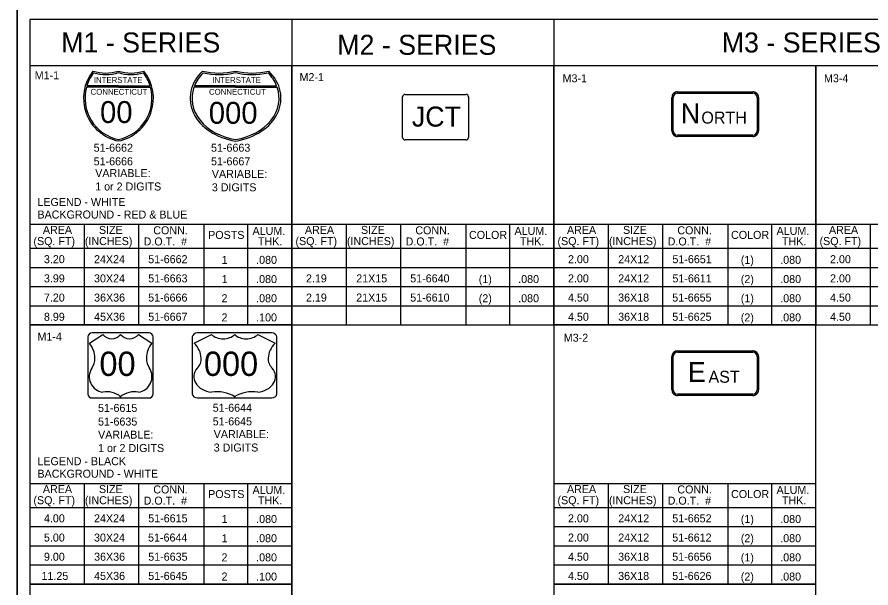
# Model space of a CAD drawing. Extents: x 0 to 2011, y -71 to 1183.
# Drawn here: x 0 to 341.3, y 164 to 392.2 of the extents above; entities that cross this region are included whole.
import ezdxf

# ---------------------------------------------------------------- set-up
doc = ezdxf.new("R2010")
doc.units = 0
for name, color, linetype in [('CT_Border_Perimeter_Shape', 7, 'Continuous'), ('CT_Construction', 7, 'Continuous'), ('Default', 7, 'Continuous'), ('Level 1', 7, 'Continuous'), ('Level 2', 7, 'Continuous'), ('Level 22', 7, 'Continuous'), ('Level 5', 7, 'Continuous')]:
    doc.layers.add(name, color=color, linetype=linetype)

msp = doc.modelspace()

# ---------------------------------------------------------------- linework, layer by layer
at = {"layer": 'CT_Border_Perimeter_Shape'}
msp.add_lwpolyline([(0, -0.97), (1270, -0.97), (1270, 829.03), (0, 829.03)], close=True, dxfattribs=at)
at = {"layer": 'CT_Construction'}
msp.add_lwpolyline([(0, 829.03), (1270, 829.03), (1270, 59.03), (0, 59.03)], close=True, dxfattribs=at)
at = {"layer": 'Default'}
for p, q in [((1262.03, 391.26), (5.05, 391.26)), ((28.92, 261.8), (34.26, 265.36)), ((48.53, 265.36), (53.87, 261.8)), ((70.77, 261.8), (77.71, 265.36)), ((96.26, 265.36), (103.2, 261.8)), ((41.36, 239.91), (41.39, 240.44)), ((41.4, 240.45), (41.37, 239.91)), ((54.37, 241.54), (54.37, 241.54)), ((86.94, 239.91), (86.99, 240.44)), ((87, 240.45), (86.96, 239.91)), ((103.86, 241.54), (103.86, 241.54))]:
    msp.add_line(p, q, dxfattribs=at)
for points in [[(28.35, 264.31), (28.35, 241.54)], [(52.74, 265.93), (29.97, 265.93)], [(54.37, 241.54), (54.37, 264.31)], [(70.03, 264.31), (70.03, 241.54)], [(101.74, 265.93), (72.14, 265.93)], [(103.86, 241.54), (103.86, 264.31)], [(29.97, 239.91), (41.36, 239.91)], [(41.37, 239.91), (52.74, 239.91)], [(72.14, 239.91), (86.94, 239.91)], [(86.96, 239.91), (101.74, 239.91)]]:
    msp.add_lwpolyline(points, dxfattribs=at)
for centre, radius, start, end in [((29.97, 264.31), 1.63, 90, 180), ((37.82, 267.99), 4.43, 216.4301, 323.5699), ((44.96, 267.99), 4.43, 216.4301, 323.5699), ((52.74, 264.31), 1.63, 0, 90), ((21.8, 255.89), 9.26, 359.7244, 39.6938), ((60.99, 255.89), 9.26, 140.3062, 180.2756), ((25.5, 255.33), 5.58, 320.9727, 5.2852), ((57.28, 255.33), 5.58, 174.7148, 219.0273), ((35.12, 248.44), 6.27, 147.4137, 262.1164), ((47.67, 248.44), 6.27, 277.8836, 32.5863), ((36, 234), 8.4, 50.0419, 101.9529), ((46.79, 234), 8.4, 78.0471, 129.856), ((29.97, 241.54), 1.63, 180, 270), ((52.74, 241.54), 1.63, 270, 360)]:
    msp.add_arc(centre, radius, start, end, dxfattribs=at)
for centre, major_axis, start_param, end_param in [((72.14, 264.31), (-2.11, 0), 4.712389, 6.283185), ((82.35, 267.99), (-5.76, 0), 0.635825, 2.505767), ((91.62, 267.99), (5.76, 0), 3.777418, 5.64736), ((101.74, 264.31), (2.11, 0), 0, 1.570796), ((61.51, 255.89), (12.03, 0), 6.278375, 6.975973), ((112.46, 255.89), (-12.03, 0), 5.590397, 6.287996), ((66.33, 255.33), (7.25, 0), 5.602031, 6.375429), ((107.65, 255.33), (-7.25, 0), 6.190941, 6.96434), ((78.83, 248.44), (-8.16, 0), 5.714447, 7.716386), ((95.14, 248.44), (8.16, 0), 4.849984, 6.851924), ((79.97, 234), (-10.92, 0), 4.014988, 4.921006), ((94, 234), (-10.92, 0), 4.503772, 5.408008), ((72.14, 241.54), (-2.11, 0), 0, 1.570796), ((101.74, 241.54), (2.11, 0), 4.712389, 6.283185)]:
    msp.add_ellipse(centre, major_axis=major_axis, ratio=0.769231, start_param=start_param, end_param=end_param, dxfattribs=at)
at = {"layer": 'Level 1'}
for p, q in [((264.01, 362.36), (294.13, 362.36)), ((154.13, 344.12), (154.13, 360.31)), ((155.14, 361.33), (179.44, 361.33)), ((180.45, 360.31), (180.45, 344.12)), ((261.77, 346.73), (261.77, 360.12)), ((262.34, 346.73), (262.34, 360.12)), ((264.01, 361.79), (294.13, 361.79)), ((295.8, 360.12), (295.8, 346.73)), ((296.37, 360.12), (296.37, 346.73)), ((294.13, 345.06), (264.01, 345.06)), ((179.44, 343.1), (155.14, 343.1)), ((294.13, 344.49), (264.01, 344.49)), ((261.77, 243.11), (261.77, 256.5)), ((262.34, 243.11), (262.34, 256.5)), ((264.01, 258.74), (294.13, 258.74)), ((264.01, 258.17), (294.13, 258.17)), ((295.8, 256.5), (295.8, 243.11)), ((296.37, 256.5), (296.37, 243.11)), ((29.97, 239.91), (29.97, 239.91)), ((72.86, 239.91), (72.86, 239.91)), ((294.13, 241.44), (264.01, 241.44)), ((294.13, 240.87), (264.01, 240.87))]:
    msp.add_line(p, q, dxfattribs=at)
for centre, radius, start, end in [((264.01, 360.12), 2.24, 90, 180.0015), ((294.13, 360.12), 2.24, 359.9993, 90), ((155.14, 360.31), 1.01, 90, 180), ((179.44, 360.31), 1.01, 0, 90), ((264.01, 360.12), 1.67, 90, 180), ((294.13, 360.12), 1.67, 0, 90), ((264.01, 346.73), 2.24, 179.998, 270), ((264.01, 346.73), 1.67, 180, 270), ((294.13, 346.73), 1.67, 270, 360), ((294.13, 346.73), 2.24, 270, 0.0005), ((155.14, 344.12), 1.01, 180, 270), ((179.44, 344.12), 1.01, 270, 360), ((264.01, 256.5), 2.24, 90, 180.0015), ((264.01, 256.5), 1.67, 90, 180), ((294.13, 256.5), 2.24, 359.9993, 90), ((294.13, 256.5), 1.67, 0, 90), ((264.01, 243.11), 2.24, 179.998, 270), ((264.01, 243.11), 1.67, 180, 270), ((294.13, 243.11), 1.67, 270, 360), ((294.13, 243.11), 2.24, 270, 0.0005)]:
    msp.add_arc(centre, radius, start, end, dxfattribs=at)
at = {"layer": 'Level 2'}
for p, q in [((40.52, 364.2), (27.73, 364.2)), ((40.52, 364.79), (27.9, 364.79)), ((40.52, 364.79), (53.15, 364.79)), ((40.52, 364.2), (53.32, 364.2)), ((87.34, 364.2), (70.71, 364.2)), ((87.34, 364.79), (70.93, 364.79)), ((87.34, 364.79), (103.76, 364.79)), ((87.34, 364.2), (103.98, 364.2)), ((5.05, 309.4), (109.8, 309.4)), ((26.8, 309.4), (26.8, 269.13)), ((48.55, 309.4), (48.55, 269.13)), ((74.65, 309.4), (74.65, 269.13)), ((92.05, 309.4), (92.05, 269.13)), ((109.8, 309.4), (214.55, 309.4)), ((131.55, 309.4), (131.55, 269.13)), ((153.3, 309.4), (153.3, 269.13)), ((179.4, 309.4), (179.4, 269.13)), ((196.8, 309.4), (196.8, 269.13)), ((214.55, 309.4), (319.3, 309.4)), ((236.3, 309.4), (236.3, 269.13)), ((258.05, 309.4), (258.05, 269.13)), ((284.15, 309.4), (284.15, 269.13)), ((301.55, 309.4), (301.55, 269.13)), ((319.3, 309.4), (424.05, 309.4)), ((341.05, 309.4), (341.05, 269.13)), ((5.05, 299.81), (109.8, 299.81)), ((109.8, 299.81), (214.55, 299.81)), ((214.55, 299.81), (319.3, 299.81)), ((319.3, 299.81), (424.05, 299.81)), ((5.05, 292.14), (109.8, 292.14)), ((109.8, 292.14), (214.55, 292.14)), ((214.55, 292.14), (319.3, 292.14)), ((319.3, 292.14), (424.05, 292.14)), ((5.05, 284.47), (109.8, 284.47)), ((109.8, 284.47), (214.55, 284.47)), ((214.55, 284.47), (319.3, 284.47)), ((319.3, 284.47), (424.05, 284.47)), ((5.05, 276.8), (109.8, 276.8)), ((109.8, 276.8), (214.55, 276.8)), ((214.55, 276.8), (319.3, 276.8)), ((319.3, 276.8), (424.05, 276.8)), ((5.05, 205.78), (109.8, 205.78)), ((26.8, 205.78), (26.8, 165.5)), ((48.55, 205.78), (48.55, 165.5)), ((74.65, 205.78), (74.65, 165.5)), ((92.05, 205.78), (92.05, 165.5)), ((214.55, 205.78), (319.3, 205.78)), ((236.3, 205.78), (236.3, 165.5)), ((258.05, 205.78), (258.05, 165.5)), ((284.15, 205.78), (284.15, 165.5)), ((301.55, 205.78), (301.55, 165.5)), ((5.05, 196.19), (109.8, 196.19)), ((214.55, 196.19), (319.3, 196.19)), ((5.05, 188.52), (109.8, 188.52)), ((214.55, 188.52), (319.3, 188.52)), ((5.05, 180.85), (109.8, 180.85)), ((214.55, 180.85), (319.3, 180.85)), ((5.05, 173.18), (109.8, 173.18)), ((214.55, 173.18), (319.3, 173.18))]:
    msp.add_line(p, q, dxfattribs=at)
for points in [[(109.8, 372.75), (5.05, 372.75), (5.05, 269.13), (109.8, 269.13)], [(214.55, 372.75), (109.8, 372.75), (109.8, 269.13), (214.55, 269.13)], [(319.3, 372.75), (214.55, 372.75), (214.55, 269.13), (319.3, 269.13)], [(424.05, 372.75), (319.3, 372.75), (319.3, 269.13), (424.05, 269.13)], [(109.8, 269.13), (5.05, 269.13), (5.05, 165.5), (109.8, 165.5)], [(319.3, 269.13), (214.55, 269.13), (214.55, 165.5), (319.3, 165.5)], [(109.8, 165.5), (5.05, 165.5), (5.05, 61.88), (109.8, 61.88)], [(319.3, 165.5), (214.55, 165.5), (214.55, 61.88), (319.3, 61.88)]]:
    msp.add_lwpolyline(points, close=True, dxfattribs=at)
for centre, radius, start, end in [((44.02, 359.78), 17.46, 141.669, 258.4631), ((44.02, 359.78), 16.88, 142.9959, 162.7368), ((35.42, 387.31), 17.46, 253.0091, 286.9909), ((35.42, 387.31), 18.04, 254.2923, 286.427), ((37.03, 359.78), 17.46, 281.5369, 38.331), ((45.63, 387.31), 17.46, 253.0091, 286.9909), ((45.63, 387.31), 18.04, 253.573, 285.7077), ((37.03, 359.78), 16.88, 17.2632, 37.0041), ((44.02, 359.78), 16.88, 164.7947, 258.0595), ((37.03, 359.78), 16.88, 281.9405, 15.2053)]:
    msp.add_arc(centre, radius, start, end, dxfattribs=at)
for centre, major_axis, start_param, end_param in [((91.88, 359.78), (22.7, 0), 2.472591, 4.511031), ((91.88, 359.78), (21.94, 0), 2.495749, 2.840293), ((80.71, 387.31), (22.7, 0), 4.415841, 5.008937), ((80.71, 387.31), (23.46, 0), 4.438239, 4.999095), ((82.8, 359.78), (-22.7, 0), 1.772154, 3.810595), ((93.98, 387.31), (22.7, 0), 4.415841, 5.008937), ((93.98, 387.31), (23.46, 0), 4.425683, 4.986539), ((82.8, 359.78), (-21.94, 0), 3.442893, 3.787436), ((91.88, 359.78), (21.94, 0), 2.876209, 4.503987), ((82.8, 359.78), (-21.94, 0), 1.779198, 3.406976)]:
    msp.add_ellipse(centre, major_axis=major_axis, ratio=0.769231, start_param=start_param, end_param=end_param, dxfattribs=at)
at = {"layer": 'Level 5'}
for p, q in [((5.05, 391.26), (5.05, 61.88)), ((109.8, 391.26), (109.8, 61.88)), ((214.55, 391.26), (214.55, 61.88))]:
    msp.add_line(p, q, dxfattribs=at)
msp.add_lwpolyline([(5.05, 391.26), (5.05, 372.75)], dxfattribs=at)

# ---------------------------------------------------------------- texts
at = {"layer": 'Level 1'}
for s, p in [('M1 - SERIES', (17.63, 378.07)), ('M3 - SERIES', (281.7, 378.07)), ('M2 - SERIES', (127.99, 377.13)), ('N', (265.34, 349.79)), ('E', (268.19, 246.32))]:
    msp.add_text(s, height=8, dxfattribs=at).set_placement(p)
at = {"layer": 'Level 2'}
for s, height, p in [('M1-1', 3.2, (7.05, 367.33)), ('M2-1', 3.2, (112.92, 366.62)), ('M3-1', 3.2, (218.08, 366.15)), ('M3-4', 3.2, (322.57, 366.15)), ('INTERSTATE', 2.333, (30.71, 365.89)), ('INTERSTATE', 2.333, (78.06, 365.89)), ('CONNECTICUT', 2.3328, (29.37, 361.17)), ('CONNECTICUT', 2.3328, (76.72, 361.17)), ('00', 8.748, (33.16, 349.87)), ('000', 8.748, (76.63, 349.56)), ('JCT', 8, (157.82, 348.43)), ('ORTH', 4.8, (273.55, 349.63)), ('51-6662', 3.2, (30.62, 338.39)), ('51-6663', 3.2, (77.53, 338.39)), ('51-6666', 3.2, (30.62, 332.94)), ('51-6667', 3.2, (77.53, 332.94)), ('VARIABLE: ', 3.2, (31.23, 328.24)), ('VARIABLE: ', 3.2, (77.86, 327.92)), ('1 or 2 DIGITS', 3.2, (31.23, 322.88)), ('3 DIGITS', 3.2, (77.86, 322.56)), ('LEGEND - WHITE', 3.2, (8.13, 316.67)), ('BACKGROUND - RED & BLUE', 3.2, (8.13, 311.67)), ('AREA', 3.2, (10.32, 305.52)), ('SIZE', 3.2, (32.73, 305.52)), ('CONN.', 3.2, (54.45, 305.37)), ('ALUM.', 3.2, (94.12, 305.14)), ('AREA', 3.2, (115.07, 305.52)), ('SIZE', 3.2, (137.48, 305.52)), ('CONN.', 3.2, (159.2, 305.37)), ('ALUM.', 3.2, (198.86, 305.14)), ('AREA', 3.2, (219.82, 305.52)), ('SIZE', 3.2, (242.23, 305.52)), ('CONN.', 3.2, (263.95, 305.37)), ('ALUM.', 3.2, (303.61, 305.14)), ('AREA', 3.2, (324.56, 305.52)), ('(SQ. FT)', 3.2, (6.54, 301.05)), ('(INCHES)', 3.2, (27.1, 301.05)), ('D.O.T.  #', 3.2, (50.59, 300.9)), ('POSTS', 3.2, (76.38, 303.52)), ('THK.', 3.2, (96.29, 301)), ('(SQ. FT)', 3.2, (111.29, 301.05)), ('(INCHES)', 3.2, (131.85, 301.05)), ('D.O.T.  #', 3.2, (155.33, 300.9)), ('COLOR', 3.2, (180.67, 303.52)), ('THK.', 3.2, (201.04, 301)), ('(SQ. FT)', 3.2, (216.03, 301.05)), ('(INCHES)', 3.2, (236.6, 301.05)), ('D.O.T.  #', 3.2, (260.08, 300.9)), ('COLOR', 3.2, (285.42, 303.52)), ('THK.', 3.2, (305.79, 301)), ('(SQ. FT)', 3.2, (320.78, 301.05)), ('M1-4', 3.2, (8.15, 262.85)), ('M3-2', 3.2, (218.55, 262.41)), ('AST', 4.8, (276.4, 246.01)), ('51-6615', 3.2, (32.36, 234.33)), ('51-6644', 3.2, (78.21, 234.41)), ('51-6635', 3.2, (32.36, 228.88)), ('51-6645', 3.2, (78.21, 228.96)), ('VARIABLE: ', 3.2, (32.38, 223.66)), ('VARIABLE: ', 3.2, (78.61, 223.86)), ('1 or 2 DIGITS', 3.2, (32.38, 218.3)), ('3 DIGITS', 3.2, (78.61, 218.5)), ('LEGEND - BLACK', 3.2, (8.13, 213.04)), ('BACKGROUND - WHITE', 3.2, (8.13, 208.04)), ('AREA', 3.2, (10.32, 201.9)), ('SIZE', 3.2, (32.73, 201.9)), ('CONN.', 3.2, (54.45, 201.74)), ('AREA', 3.2, (219.82, 201.9)), ('SIZE', 3.2, (242.23, 201.9)), ('CONN.', 3.2, (263.95, 201.74)), ('POSTS', 3.2, (76.38, 199.9)), ('ALUM.', 3.2, (94.12, 201.52)), ('COLOR', 3.2, (285.42, 199.9)), ('ALUM.', 3.2, (303.61, 201.52)), ('(SQ. FT)', 3.2, (6.54, 197.43)), ('(INCHES)', 3.2, (27.1, 197.43)), ('D.O.T.  #', 3.2, (50.59, 197.27)), ('THK.', 3.2, (96.29, 197.38)), ('(SQ. FT)', 3.2, (216.03, 197.43)), ('(INCHES)', 3.2, (236.6, 197.43)), ('D.O.T.  #', 3.2, (260.08, 197.27)), ('THK.', 3.2, (305.79, 197.38))]:
    msp.add_text(s, height=height, dxfattribs=at).set_placement(p)
at = {"layer": 'Level 22'}
for s, p in [('00', (32.92, 248.73)), ('000', (74.69, 248.73))]:
    msp.add_text(s, height=9.72, dxfattribs=at).set_placement(p)
at = {"layer": 'Level 5'}
for s, p in [(' 3.20', (9.55, 293.81)), ('24X24', (30.76, 293.81)), ('51-6662', (52.43, 293.81)), (' 2.00', (219.05, 293.81)), ('24X12', (240.32, 293.81)), ('51-6651', (261.98, 293.81)), (' 2.00', (323.8, 293.81)), ('1', (81.79, 293.55)), ('.080', (95.57, 293.55)), ('(1)', (289.31, 293.55)), ('.080', (305.07, 293.55)), (' 3.99', (9.55, 286.14)), ('30X24', (30.76, 286.14)), ('51-6663', (52.43, 286.14)), ('1', (81.79, 285.87)), ('.080', (95.57, 285.87)), (' 2.19', (114.3, 286.14)), ('21X15', (135.57, 286.14)), ('51-6640', (157.17, 286.14)), ('(1)', (184.56, 285.87)), ('.080', (200.32, 285.87)), (' 2.00', (219.05, 286.14)), ('24X12', (240.32, 286.14)), ('51-6611', (261.98, 286.14)), ('(2)', (289.31, 285.87)), ('.080', (305.07, 285.87)), (' 2.00', (323.8, 286.14)), (' 7.20', (9.55, 278.47)), ('36X36', (30.79, 278.47)), ('51-6666', (52.4, 278.47)), ('2', (81.73, 278.2)), ('.080', (95.57, 278.2)), (' 2.19', (114.3, 278.47)), ('21X15', (135.57, 278.47)), ('51-6610', (157.17, 278.47)), ('(2)', (184.56, 278.2)), ('.080', (200.32, 278.2)), (' 4.50', (219.05, 278.47)), ('36X18', (240.29, 278.47)), ('51-6655', (261.92, 278.47)), ('(1)', (289.31, 278.2)), ('.080', (305.07, 278.2)), (' 4.50', (323.8, 278.47)), (' 8.99', (9.55, 270.79)), ('45X36', (30.79, 270.79)), ('51-6667', (52.43, 270.79)), ('2', (81.73, 270.53)), ('.100', (95.57, 270.53)), (' 4.50', (219.05, 270.79)), ('36X18', (240.29, 270.79)), ('51-6625', (261.92, 270.79)), ('(2)', (289.31, 270.53)), ('.080', (305.07, 270.53)), (' 4.50', (323.8, 270.79)), (' 4.00', (9.55, 190.19)), ('24X24', (30.76, 190.19)), ('51-6615', (52.43, 190.19)), ('1', (81.79, 189.92)), ('.080', (95.57, 189.92)), (' 2.00', (219.05, 190.19)), ('24X12', (240.32, 190.19)), ('51-6652', (261.92, 190.19)), ('(1)', (289.31, 189.92)), ('.080', (305.07, 189.92)), (' 5.00', (9.55, 182.51)), ('30X24', (30.76, 182.51)), ('51-6644', (52.37, 182.51)), ('1', (81.79, 182.25)), ('.080', (95.57, 182.25)), (' 2.00', (219.05, 182.51)), ('24X12', (240.32, 182.51)), ('51-6612', (261.92, 182.51)), ('(2)', (289.31, 182.25)), ('.080', (305.07, 182.25)), (' 9.00', (9.55, 174.84)), ('36X36', (30.79, 174.84)), ('51-6635', (52.43, 174.84)), ('2', (81.73, 174.58)), ('.080', (95.57, 174.58)), (' 4.50', (219.05, 174.84)), ('36X18', (240.29, 174.84)), ('51-6656', (261.89, 174.84)), ('(1)', (289.31, 174.58)), ('.080', (305.07, 174.58)), ('11.25', (9.77, 167.17)), ('45X36', (30.79, 167.17)), ('51-6645', (52.43, 167.17)), ('2', (81.73, 166.91)), ('.100', (95.57, 166.91)), (' 4.50', (219.05, 167.17)), ('36X18', (240.29, 167.17)), ('51-6626', (261.89, 167.17)), ('(2)', (289.31, 166.91)), ('.080', (305.07, 166.91))]:
    msp.add_text(s, height=3.2, dxfattribs=at).set_placement(p)

doc.saveas('drawing.dxf')
